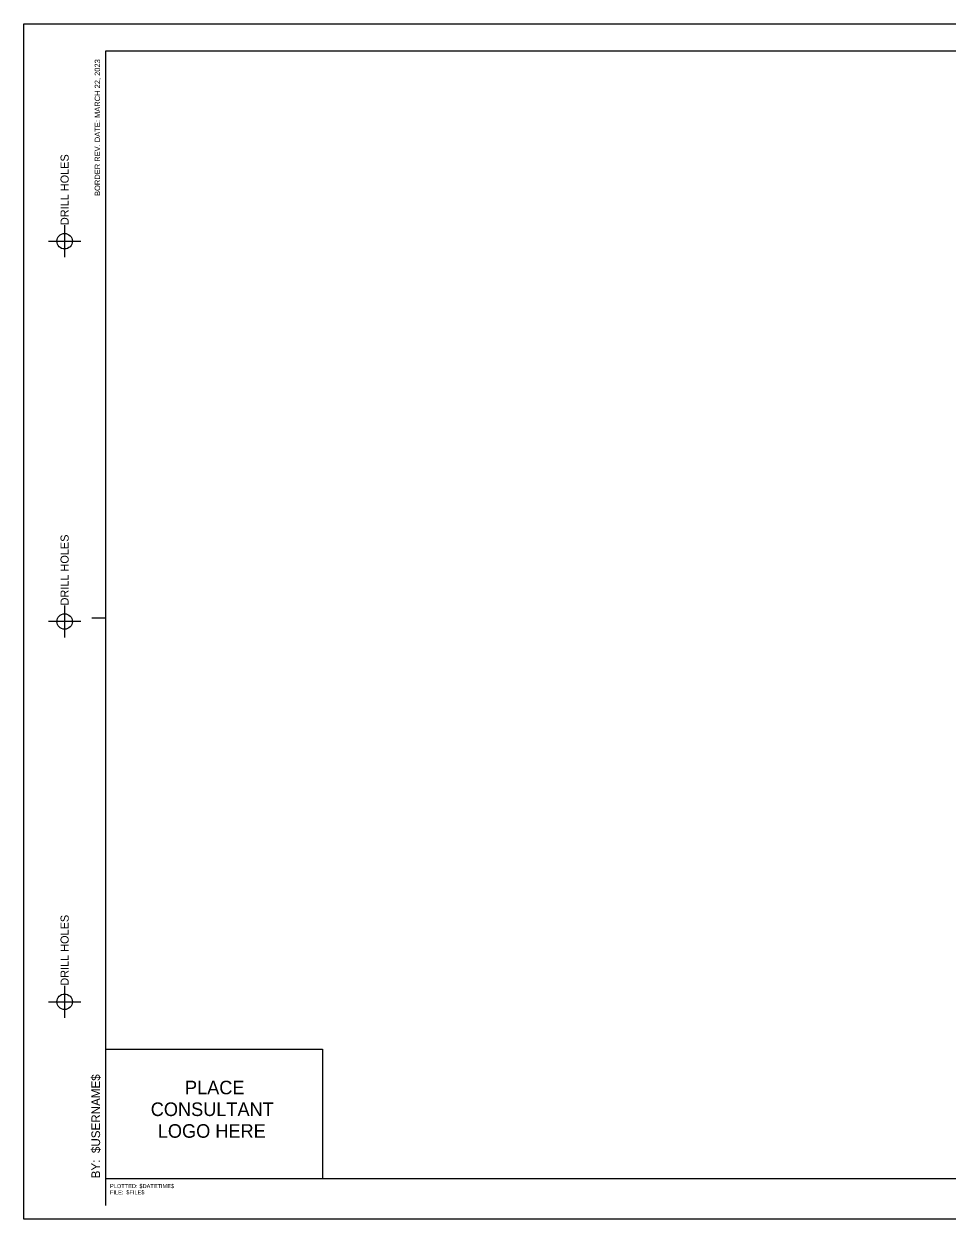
# Model space of a CAD drawing. Extents: x 0 to 34, y 0 to 22.
# Drawn here: x 0 to 17, y 0 to 22 of the extents above; entities that cross this region are included whole.
import ezdxf

# ---------------------------------------------------------------- set-up
doc = ezdxf.new("R2010")
doc.units = 0
for name, color, linetype in [('BORD-LINE', 7, 'Continuous'), ('CONS-LINE', 7, 'Continuous'), ('TTLB-TEXT', 7, 'Continuous'), ('USER-LINE', 7, 'Continuous'), ('USER-PAGE', 7, 'Continuous'), ('USER-TEXT', 7, 'Continuous')]:
    doc.layers.add(name, color=color, linetype=linetype)

msp = doc.modelspace()

# ---------------------------------------------------------------- linework, layer by layer
at = {"layer": 'BORD-LINE'}
for p, q in [((1.5, 11.062), (1.25, 11.062)), ((1.5, 0.75), (1.5, 0.25))]:
    msp.add_line(p, q, dxfattribs=at)
msp.add_lwpolyline([(1.5, 0.75), (33.5, 0.75), (33.5, 21.5), (1.5, 21.5)], close=True, dxfattribs=at)
at = {"layer": 'CONS-LINE'}
for p, q in [((1.5, 3.125), (5.5, 3.125)), ((5.5, 3.125), (5.5, 0.75))]:
    msp.add_line(p, q, dxfattribs=at)
at = {"layer": 'TTLB-TEXT'}
for p, q in [((0.75, 18.296), (0.75, 18)), ((0.454, 18), (1.046, 18)), ((0.75, 18), (0.75, 17.704)), ((0.75, 11.296), (0.75, 11)), ((1.046, 11), (0.454, 11)), ((0.75, 11), (0.75, 10.704)), ((0.75, 4.296), (0.75, 3.704)), ((0.454, 4), (1.046, 4))]:
    msp.add_line(p, q, dxfattribs=at)
for centre in [(0.75, 18), (0.75, 11), (0.75, 4)]:
    msp.add_circle(centre, 0.143, dxfattribs=at)
at = {"layer": 'USER-PAGE'}
msp.add_lwpolyline([(0, 22), (34, 22), (34, 0), (0, 0)], close=True, dxfattribs=at)

# ---------------------------------------------------------------- texts
at = {"layer": 'TTLB-TEXT'}
for s, height, rotation, p in [('$USERNAME$', 0.16, 90, (1.403, 1.215)), ('BY:', 0.16, 90, (1.403, 0.75)), ('PLOTTED:', 0.075, 360, (1.586, 0.57)), ('FILE:', 0.075, 360, (1.586, 0.455)), ('$FILE$', 0.075, 360, (1.885, 0.455)), ('$DATETIME$', 0.075, 360, (2.127, 0.57))]:
    msp.add_text(s, height=height, rotation=rotation, dxfattribs=at).set_placement(p)
at = {"layer": 'USER-LINE'}
for s, p in [('PLACE', (2.966, 2.297)), ('CONSULTANT', (2.336, 1.897)), ('LOGO HERE', (2.466, 1.497))]:
    msp.add_text(s, height=0.25, dxfattribs=at).set_placement(p)
at = {"layer": 'USER-TEXT'}
for s, height, p in [('BORDER REV. DATE: MARCH 22, 2023', 0.1, (1.403, 18.833)), ('DRILL HOLES', 0.15, (0.825, 18.296)), ('DRILL HOLES', 0.15, (0.825, 11.296)), ('DRILL HOLES', 0.15, (0.825, 4.296))]:
    msp.add_text(s, height=height, rotation=90, dxfattribs=at).set_placement(p)

doc.saveas('drawing.dxf')
